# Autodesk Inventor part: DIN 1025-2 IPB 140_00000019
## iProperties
Created: 2006-02
Part Number: DIN 1025-2 IPB 140_00000019
Material: Default
Document SubType Name: Modeling
Designer: 40664
Manufacturer: Standard
Standards Organization: Custom
Stock Number: DIN 1025-2 IPB 140
Mass: 14905.7 g
Surface Area: 28033.2 cm^2
Volume: 14905.7 cm^3
Density: 1 g/cm^3
G_L: 3470.000 mm
G_W: 140.000 mm
G_H: 140.000 mm
AFG_Item: IPB 140
CSToolsMass: 15.0
CSToolsVolume: 14905705.0
CSToolsArea: 28033.0
Author: 40664
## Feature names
1. AFG_Detailed_DIN 1025-2 IPB 140_00000019 [Extrusion]
2. AFG_Simplified_DIN 1025-2 IPB 140_00000019 [Extrusion]
